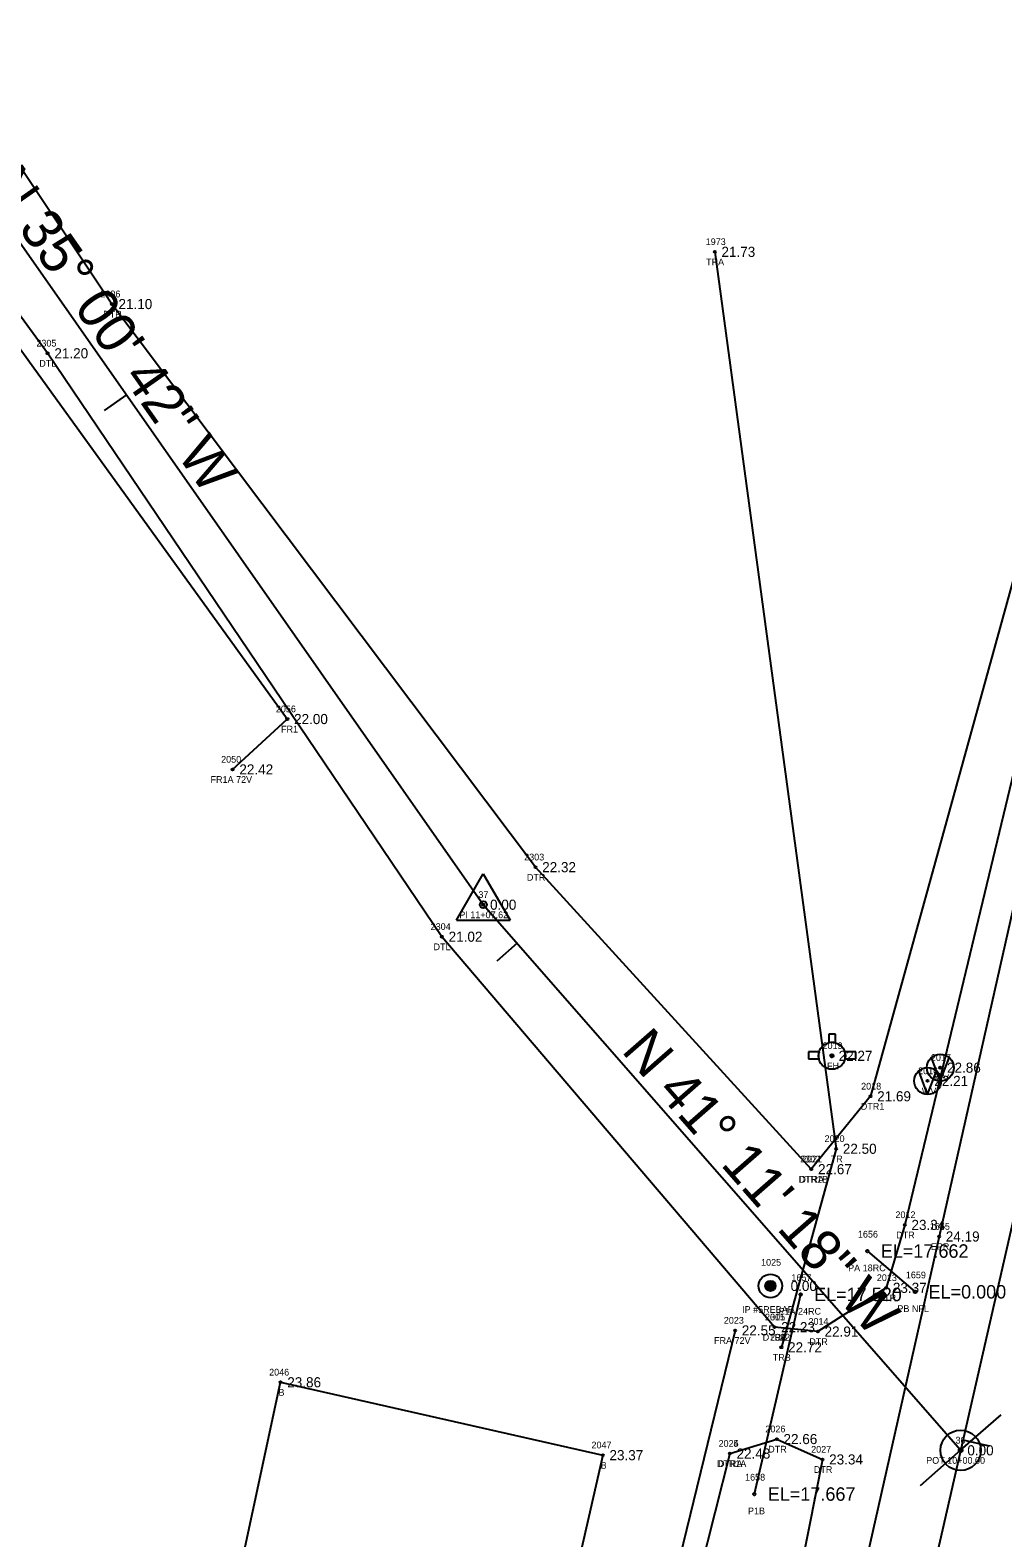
# Model space of a CAD drawing. Extents: x 2654414 to 2656963, y 761776 to 764965.
# Drawn here: x 2655361.5 to 2655506, y 762284.8 to 762508.6 of the extents above; entities that cross this region are included whole.
import ezdxf

# ---------------------------------------------------------------- set-up
doc = ezdxf.new("R2010")
doc.units = 0
for name, color, linetype in [('Default', 7, 'Continuous'), ('RD_EX_Bldg', 7, 'Continuous'), ('RD_EX_Bldg_txCode', 7, 'Continuous'), ('RD_EX_DR_Pipe', 7, 'Continuous'), ('RD_EX_DR_Pipe_txCode', 7, 'Continuous'), ('RD_EX_DV_Prop_txCode', 7, 'Continuous'), ('RD_EX_DV_PropPin', 7, 'Continuous'), ('RD_EX_Fence_Other', 7, 'Continuous'), ('RD_EX_Fence_Other_txCode', 7, 'Continuous'), ('RD_EX_H2O', 7, 'Continuous'), ('RD_EX_H2O_txCode', 7, 'Continuous'), ('RD_EX_Road', 7, 'Continuous'), ('RD_EX_Road_txCode', 7, 'Continuous'), ('RD_EX_TX_Bldg_ELEV', 7, 'Continuous'), ('RD_EX_TX_DV_Prop_ELEV', 7, 'Continuous'), ('RD_EX_TX_Fence_Other_ELEV', 7, 'Continuous'), ('RD_EX_TX_H2O_ELEV', 7, 'Continuous'), ('RD_EX_TX_Road_ELEV', 7, 'Continuous'), ('RD_EX_TX_UT_ELEV', 7, 'Continuous'), ('RD_EX_TX_VEG_ELEV', 7, 'Continuous'), ('RD_EX_UT', 7, 'Continuous'), ('RD_EX_UT_txCode', 7, 'Continuous'), ('RD_EX_VEG', 7, 'Continuous'), ('RD_EX_VEG_txCode', 7, 'Continuous'), ('RD_HC_Cl', 7, 'Continuous'), ('RD_HC_Data', 7, 'Continuous'), ('RD_HC_Data_Tic', 7, 'Continuous'), ('RD_HC_Survey_ELEV', 7, 'Continuous'), ('RD_HC_txCode', 7, 'Continuous'), ('RD_SMD_Locator', 7, 'Continuous'), ('RD_TX_Pipe_ElevEX', 7, 'Continuous')]:
    doc.layers.add(name, color=color, linetype=linetype)

msp = doc.modelspace()

# ---------------------------------------------------------------- linework, layer by layer
at = {"layer": 'Default'}
for p, q in [((2656050.51, 764712.37), (2655383.26, 761787.51)), ((2655428.81, 762378.81), (2655313.91, 762542.84)), ((2655499.68, 762297.82), (2655428.81, 762378.81))]:
    msp.add_line(p, q, dxfattribs=at)
at = {"layer": 'RD_EX_Bldg'}
msp.add_lwpolyline([(2655437.72, 762258.29), (2655390.48, 762269.63), (2655398.7, 762307.92), (2655446.54, 762297.1), (2655437.72, 762258.29)], dxfattribs=at)
at = {"layer": 'RD_EX_DR_Pipe'}
for p, q in [((2655485.83, 762327.4), (2655492.92, 762321.35)), ((2655475.93, 762320.96), (2655469.05, 762291.33))]:
    msp.add_line(p, q, dxfattribs=at)
at = {"layer": 'RD_EX_DV_PropPin'}
for p, q in [((2655470.7, 762322.02), (2655470.7, 762322.41)), ((2655470.74, 762321.92), (2655470.74, 762322.51)), ((2655470.77, 762321.85), (2655470.77, 762322.59)), ((2655470.81, 762321.79), (2655470.81, 762322.64)), ((2655470.84, 762321.74), (2655470.84, 762322.69)), ((2655470.88, 762321.7), (2655470.88, 762322.73)), ((2655470.91, 762321.67), (2655470.91, 762322.77)), ((2655470.95, 762321.63), (2655470.95, 762322.8)), ((2655470.98, 762321.61), (2655470.98, 762322.83)), ((2655471.02, 762321.58), (2655471.02, 762322.85)), ((2655471.05, 762321.56), (2655471.05, 762322.87)), ((2655471.09, 762321.54), (2655471.09, 762322.89)), ((2655471.12, 762321.52), (2655471.12, 762322.91)), ((2655471.16, 762321.51), (2655471.16, 762322.92)), ((2655471.19, 762321.5), (2655471.19, 762322.94)), ((2655471.23, 762321.48), (2655471.23, 762322.95)), ((2655471.26, 762321.48), (2655471.26, 762322.96)), ((2655471.3, 762321.47), (2655471.3, 762322.96)), ((2655471.33, 762321.46), (2655471.33, 762322.97)), ((2655471.37, 762321.46), (2655471.37, 762322.97)), ((2655471.4, 762321.46), (2655471.4, 762322.98)), ((2655471.44, 762321.46), (2655471.44, 762322.98)), ((2655471.47, 762321.46), (2655471.47, 762322.98)), ((2655471.51, 762321.46), (2655471.51, 762322.97)), ((2655471.54, 762321.46), (2655471.54, 762322.97)), ((2655471.58, 762321.47), (2655471.58, 762322.96)), ((2655471.61, 762321.48), (2655471.61, 762322.96)), ((2655471.65, 762321.48), (2655471.65, 762322.95)), ((2655471.68, 762321.5), (2655471.68, 762322.94)), ((2655471.72, 762321.51), (2655471.72, 762322.92)), ((2655471.75, 762321.52), (2655471.75, 762322.91)), ((2655471.79, 762321.54), (2655471.79, 762322.89)), ((2655471.82, 762321.56), (2655471.82, 762322.87)), ((2655471.86, 762321.58), (2655471.86, 762322.85)), ((2655471.89, 762321.61), (2655471.89, 762322.83)), ((2655471.93, 762321.63), (2655471.93, 762322.8)), ((2655471.96, 762321.67), (2655471.96, 762322.77)), ((2655472, 762321.7), (2655472, 762322.73)), ((2655472.03, 762321.74), (2655472.03, 762322.69)), ((2655472.07, 762321.79), (2655472.07, 762322.64)), ((2655472.1, 762321.85), (2655472.1, 762322.59)), ((2655472.14, 762321.92), (2655472.14, 762322.51)), ((2655472.17, 762322.02), (2655472.17, 762322.41))]:
    msp.add_line(p, q, dxfattribs=at)
for radius in [1.75, 0.761]:
    msp.add_circle((2655471.44, 762322.22), radius, dxfattribs=at)
at = {"layer": 'RD_EX_Fence_Other'}
msp.add_line((2655466.19, 762315.62), (2655445.66, 762231.58), dxfattribs=at)
msp.add_lwpolyline([(2655391.59, 762398.89), (2655399.71, 762406.37), (2655283.48, 762567.29), (2655265.64, 762603.75), (2655195.17, 762709.07)], dxfattribs=at)
at = {"layer": 'RD_EX_H2O'}
msp.add_line((2655465.41, 762297.34), (2655455.23, 762257.11), dxfattribs=at)
for points in [[(2655472.03, 762316.1), (2655422.66, 762374.06), (2655364.12, 762460.66), (2655307.09, 762538.82), (2655256.59, 762623.14), (2655196.27, 762713.84), (2655205.8, 762720.91)], [(2655477.51, 762339.55), (2655436.55, 762384.38), (2655373.64, 762467.97), (2655320.48, 762547.58), (2655269.92, 762633.7), (2655205.8, 762720.91)], [(2655543.55, 762560.68), (2655539.34, 762565), (2655535.47, 762561.26), (2655533.61, 762546.63), (2655528.16, 762524.75), (2655507.6, 762427.4), (2655486.29, 762350.37), (2655477.51, 762339.55)], [(2655543.55, 762560.68), (2655534.37, 762523.92), (2655514.09, 762425.76), (2655491.38, 762331.28), (2655488.62, 762321.94), (2655478.48, 762315.45), (2655472.03, 762316.1)], [(2655465.41, 762297.34), (2655472.38, 762299.49), (2655479.16, 762296.47), (2655474.01, 762270.5), (2655462.93, 762226.04), (2655458.03, 762221.45), (2655449.91, 762220.5), (2655446.47, 762222.97), (2655455.23, 762257.11)]]:
    msp.add_lwpolyline(points, dxfattribs=at)
at = {"layer": 'RD_EX_Road'}
msp.add_lwpolyline([(2655700.99, 763232.28), (2655693.55, 763198.57), (2655671.65, 763102.04), (2655649.04, 763001.06), (2655627.27, 762906.23), (2655605, 762809.37), (2655598.99, 762783.09), (2655583.65, 762714.14), (2655561.97, 762618.32), (2655556.36, 762593.84), (2655548.11, 762557.14), (2655540.1, 762522.48), (2655518.03, 762425.04), (2655496.48, 762329.56), (2655475.55, 762236.62), (2655473.2, 762226.14), (2655466.57, 762197.5), (2655460.06, 762168.16), (2655454.26, 762143.78), (2655432.5, 762049.88), (2655410.7, 761955.51), (2655388.17, 761858.43), (2655373.5, 761793.95)], dxfattribs=at)
at = {"layer": 'RD_EX_UT'}
for p, q in [((2655480.11, 762359.6), (2655480.11, 762358.33)), ((2655481.11, 762359.6), (2655480.11, 762359.6)), ((2655481.11, 762358.31), (2655481.11, 762359.6)), ((2655478.65, 762356.95), (2655477.1, 762356.95)), ((2655477.1, 762356.95), (2655477.1, 762355.95)), ((2655477.1, 762355.95), (2655478.61, 762355.95)), ((2655484.1, 762356.95), (2655482.48, 762356.95)), ((2655482.52, 762355.95), (2655484.1, 762355.95)), ((2655484.1, 762355.95), (2655484.1, 762356.95)), ((2655496.66, 762352.63), (2655495.36, 762356.11)), ((2655496.66, 762352.63), (2655497.98, 762356.08)), ((2655494.78, 762350.66), (2655493.47, 762354.14)), ((2655494.78, 762350.66), (2655496.1, 762354.1))]:
    msp.add_line(p, q, dxfattribs=at)
for centre, radius in [((2655480.57, 762356.38), 2), ((2655480.57, 762356.38), 0.25), ((2655496.66, 762354.62), 2), ((2655494.78, 762352.65), 2)]:
    msp.add_circle(centre, radius, dxfattribs=at)
for start, end in [(74.2455, 103.2128), (163.3387, 192.315), (347.685, 16.6613)]:
    msp.add_arc((2655480.57, 762356.38), 2, start, end, dxfattribs=at)
at = {"layer": 'RD_EX_VEG'}
msp.add_lwpolyline([(2655463.17, 762475.72), (2655481.19, 762342.58), (2655473.06, 762313.11)], dxfattribs=at)
at = {"layer": 'RD_HC_Cl'}
for p, q in [((2656050.51, 764712.37), (2655383.26, 761787.51)), ((2655428.81, 762378.81), (2655313.91, 762542.84)), ((2655499.68, 762297.82), (2655428.81, 762378.81))]:
    msp.add_line(p, q, dxfattribs=at)
at = {"layer": 'RD_HC_Data'}
for p, q in [((2655424.84, 762376.52), (2655428.81, 762383.4)), ((2655428.81, 762383.4), (2655432.78, 762376.52)), ((2655424.84, 762376.52), (2655432.78, 762376.52))]:
    msp.add_line(p, q, dxfattribs=at)
for centre, radius in [((2655428.81, 762378.81), 0.529), ((2655499.68, 762297.82), 3), ((2655499.68, 762297.82), 0.282)]:
    msp.add_circle(centre, radius, dxfattribs=at)
at = {"layer": 'RD_HC_Data_Tic'}
for p, q in [((2655375.81, 762454.48), (2655372.53, 762452.18)), ((2655433.83, 762373.08), (2655430.82, 762370.44)), ((2655499.68, 762297.82), (2655505.7, 762303.09)), ((2655499.68, 762297.82), (2655493.66, 762292.56)), ((2655500.03, 762299.36), (2655503.93, 762298.47))]:
    msp.add_line(p, q, dxfattribs=at)
at = {"layer": 'RD_SMD_Locator'}
for centre, radius in [((2655463.17, 762475.72), 0.15), ((2655373.64, 762467.97), 0.15), ((2655364.12, 762460.66), 0.15), ((2655399.71, 762406.37), 0.15), ((2655391.59, 762398.89), 0.15), ((2655436.55, 762384.38), 0.15), ((2655428.81, 762378.81), 0.15), ((2655422.66, 762374.06), 0.15), ((2655480.57, 762356.38), 0.15), ((2655496.66, 762354.62), 0.15), ((2655494.78, 762352.65), 0.15), ((2655486.29, 762350.37), 0.15), ((2655481.19, 762342.58), 0.15), ((2655477.51, 762339.55), 0.15), ((2655477.51, 762339.55), 0.15), ((2655491.38, 762331.28), 0.15), ((2655496.48, 762329.56), 0.15), ((2655485.83, 762327.4), 0.2), ((2655471.44, 762322.22), 0.15), ((2655488.62, 762321.94), 0.15), ((2655475.93, 762320.96), 0.2), ((2655492.92, 762321.35), 0.2), ((2655466.19, 762315.62), 0.15), ((2655472.03, 762316.1), 0.15), ((2655472.03, 762316.1), 0.15), ((2655478.48, 762315.45), 0.15), ((2655473.06, 762313.11), 0.15), ((2655398.7, 762307.92), 0.15), ((2655472.38, 762299.49), 0.15), ((2655446.54, 762297.1), 0.15), ((2655465.41, 762297.34), 0.15), ((2655465.41, 762297.34), 0.15), ((2655499.68, 762297.82), 0.15), ((2655479.16, 762296.47), 0.15), ((2655469.05, 762291.33), 0.2)]:
    msp.add_circle(centre, radius, dxfattribs=at)

# ---------------------------------------------------------------- texts
at = {"layer": 'RD_EX_Bldg_txCode'}
for s, p in [('2046', (2655397.01, 762308.92)), ('B', (2655398.39, 762305.92)), ('2047', (2655444.87, 762298.1)), ('B', (2655446.23, 762295.1))]:
    msp.add_text(s, height=1, dxfattribs=at).set_placement(p)
at = {"layer": 'RD_EX_DR_Pipe_txCode'}
for s, p in [('1656', (2655484.43, 762329.4)), ('PA 18RC', (2655482.98, 762324.4)), ('1659', (2655491.55, 762323.35)), ('1657', (2655474.56, 762322.96)), ('P1A 24RC', (2655472.64, 762317.96)), ('PB NFL', (2655490.29, 762318.35)), ('1658', (2655467.68, 762293.33)), ('P1B', (2655468.11, 762288.33))]:
    msp.add_text(s, height=1, dxfattribs=at).set_placement(p)
at = {"layer": 'RD_EX_DV_Prop_txCode'}
for s, p in [('1025', (2655470.05, 762325.22)), ('IP #5REBAR', (2655467.24, 762318.22))]:
    msp.add_text(s, height=1, dxfattribs=at).set_placement(p)
at = {"layer": 'RD_EX_Fence_Other_txCode'}
for s, p in [('2056', (2655398.01, 762407.37)), ('FR1', (2655398.78, 762404.37)), ('2050', (2655389.88, 762399.89)), ('FR1A 72V', (2655388.31, 762396.89)), ('2023', (2655464.52, 762316.62)), ('FRA 72V', (2655463.07, 762313.62))]:
    msp.add_text(s, height=1, dxfattribs=at).set_placement(p)
at = {"layer": 'RD_EX_H2O_txCode'}
for s, p in [('2306', (2655371.95, 762468.97)), ('DTR', (2655372.37, 762465.97)), ('2305', (2655362.45, 762461.66)), ('DTL', (2655362.88, 762458.66)), ('2303', (2655434.88, 762385.38)), ('DTR', (2655435.28, 762382.38)), ('2304', (2655420.99, 762375.06)), ('DTL', (2655421.42, 762372.06)), ('2018', (2655484.91, 762351.37)), ('DTR1', (2655484.86, 762348.37)), ('2302', (2655475.84, 762340.55)), ('2021', (2655476.12, 762340.55)), ('DTR1B', (2655475.6, 762337.55)), ('DTRA', (2655475.75, 762337.55)), ('2012', (2655490, 762332.28)), ('DTR', (2655490.11, 762329.28)), ('2013', (2655487.24, 762322.94)), ('DTR', (2655487.36, 762319.94)), ('2015', (2655470.64, 762317.1)), ('2301', (2655470.64, 762317.1)), ('2014', (2655477.09, 762316.45)), ('DTRB', (2655470.29, 762314.1)), ('DTLA', (2655470.3, 762314.1)), ('DTR', (2655477.21, 762313.45)), ('2026', (2655470.69, 762300.49)), ('2024', (2655463.74, 762298.34)), ('2025', (2655463.74, 762298.34)), ('DTR', (2655471.11, 762297.49)), ('2027', (2655477.49, 762297.47)), ('DTR1A', (2655463.48, 762295.34)), ('DTRA', (2655463.65, 762295.34)), ('DTR', (2655477.89, 762294.47))]:
    msp.add_text(s, height=1, dxfattribs=at).set_placement(p)
at = {"layer": 'RD_EX_Road_txCode'}
for s, p in [('1655', (2655495.11, 762330.56)), ('EPR', (2655495.25, 762327.56))]:
    msp.add_text(s, height=1, dxfattribs=at).set_placement(p)
at = {"layer": 'RD_EX_TX_Bldg_ELEV'}
for s, p in [('23.86', (2655399.7, 762307.17)), ('23.37', (2655447.54, 762296.35))]:
    msp.add_text(s, height=1.5, dxfattribs=at).set_placement(p)
at = {"layer": 'RD_EX_TX_DV_Prop_ELEV'}
msp.add_text('0.00', height=1.5, dxfattribs=at).set_placement((2655474.44, 762321.47))
at = {"layer": 'RD_EX_TX_Fence_Other_ELEV'}
for s, p in [('22.00', (2655400.71, 762405.62)), ('22.42', (2655392.59, 762398.14)), ('22.55', (2655467.19, 762314.87))]:
    msp.add_text(s, height=1.5, dxfattribs=at).set_placement(p)
at = {"layer": 'RD_EX_TX_H2O_ELEV'}
for s, p in [('21.10', (2655374.64, 762467.22)), ('21.20', (2655365.12, 762459.91)), ('22.32', (2655437.55, 762383.63)), ('21.02', (2655423.66, 762373.31)), ('21.69', (2655487.29, 762349.62)), ('22.67', (2655478.51, 762338.8)), ('22.67', (2655478.51, 762338.8)), ('23.34', (2655492.38, 762330.53)), ('23.37', (2655489.62, 762321.19)), ('22.23', (2655473.03, 762315.35)), ('22.23', (2655473.03, 762315.35)), ('22.91', (2655479.48, 762314.7)), ('22.66', (2655473.38, 762298.74)), ('22.48', (2655466.41, 762296.59)), ('22.48', (2655466.41, 762296.59)), ('23.34', (2655480.16, 762295.72))]:
    msp.add_text(s, height=1.5, dxfattribs=at).set_placement(p)
at = {"layer": 'RD_EX_TX_Road_ELEV'}
msp.add_text('24.19', height=1.5, dxfattribs=at).set_placement((2655497.48, 762328.81))
at = {"layer": 'RD_EX_TX_UT_ELEV'}
for s, p in [('22.27', (2655481.57, 762355.63)), ('22.86', (2655497.66, 762353.87)), ('22.21', (2655495.78, 762351.9))]:
    msp.add_text(s, height=1.5, dxfattribs=at).set_placement(p)
at = {"layer": 'RD_EX_TX_VEG_ELEV'}
for s, p in [('21.73', (2655464.17, 762474.97)), ('22.50', (2655482.19, 762341.83)), ('22.72', (2655474.06, 762312.36))]:
    msp.add_text(s, height=1.5, dxfattribs=at).set_placement(p)
at = {"layer": 'RD_EX_UT_txCode'}
for s, p in [('2019', (2655479.18, 762357.38)), ('FH', (2655479.84, 762354.38)), ('2017', (2655495.27, 762355.62)), ('2016', (2655493.37, 762353.65)), ('WV', (2655495.8, 762352.62)), ('WV', (2655493.92, 762350.65))]:
    msp.add_text(s, height=1, dxfattribs=at).set_placement(p)
at = {"layer": 'RD_EX_VEG_txCode'}
for s, p in [('1973', (2655461.83, 762476.72)), ('TRA', (2655461.89, 762473.72)), ('2020', (2655479.48, 762343.58)), ('TR', (2655480.39, 762340.58)), ('2022', (2655471.39, 762314.11)), ('TRB', (2655471.79, 762311.11))]:
    msp.add_text(s, height=1, dxfattribs=at).set_placement(p)
at = {"layer": 'RD_HC_Data'}
for s, rotation, p in [('N 35%%d 00\' 42" W', 305.0116, (2655355.06, 762485.83)), ('N 41%%d 11\' 18" W', 311.1884, (2655449.18, 762357.06))]:
    msp.add_text(s, height=6, rotation=rotation, dxfattribs=at).set_placement(p)
at = {"layer": 'RD_HC_Survey_ELEV'}
for p in [(2655429.81, 762378.06), (2655500.68, 762297.07)]:
    msp.add_text('0.00', height=1.5, dxfattribs=at).set_placement(p)
at = {"layer": 'RD_HC_txCode'}
for s, p in [('37', (2655428.08, 762379.81)), ('PI 11+07.62', (2655425.25, 762376.81)), ('36', (2655498.92, 762298.82)), ('POT 10+00.00', (2655494.57, 762295.82))]:
    msp.add_text(s, height=1, dxfattribs=at).set_placement(p)
at = {"layer": 'RD_TX_Pipe_ElevEX'}
for s, p in [('EL=17.662', (2655487.83, 762326.4)), ('EL=17.520', (2655477.93, 762319.96)), ('EL=0.000', (2655494.92, 762320.35)), ('EL=17.667', (2655471.05, 762290.33))]:
    msp.add_text(s, height=2, dxfattribs=at).set_placement(p)

doc.saveas('drawing.dxf')
